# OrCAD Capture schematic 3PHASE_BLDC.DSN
size B
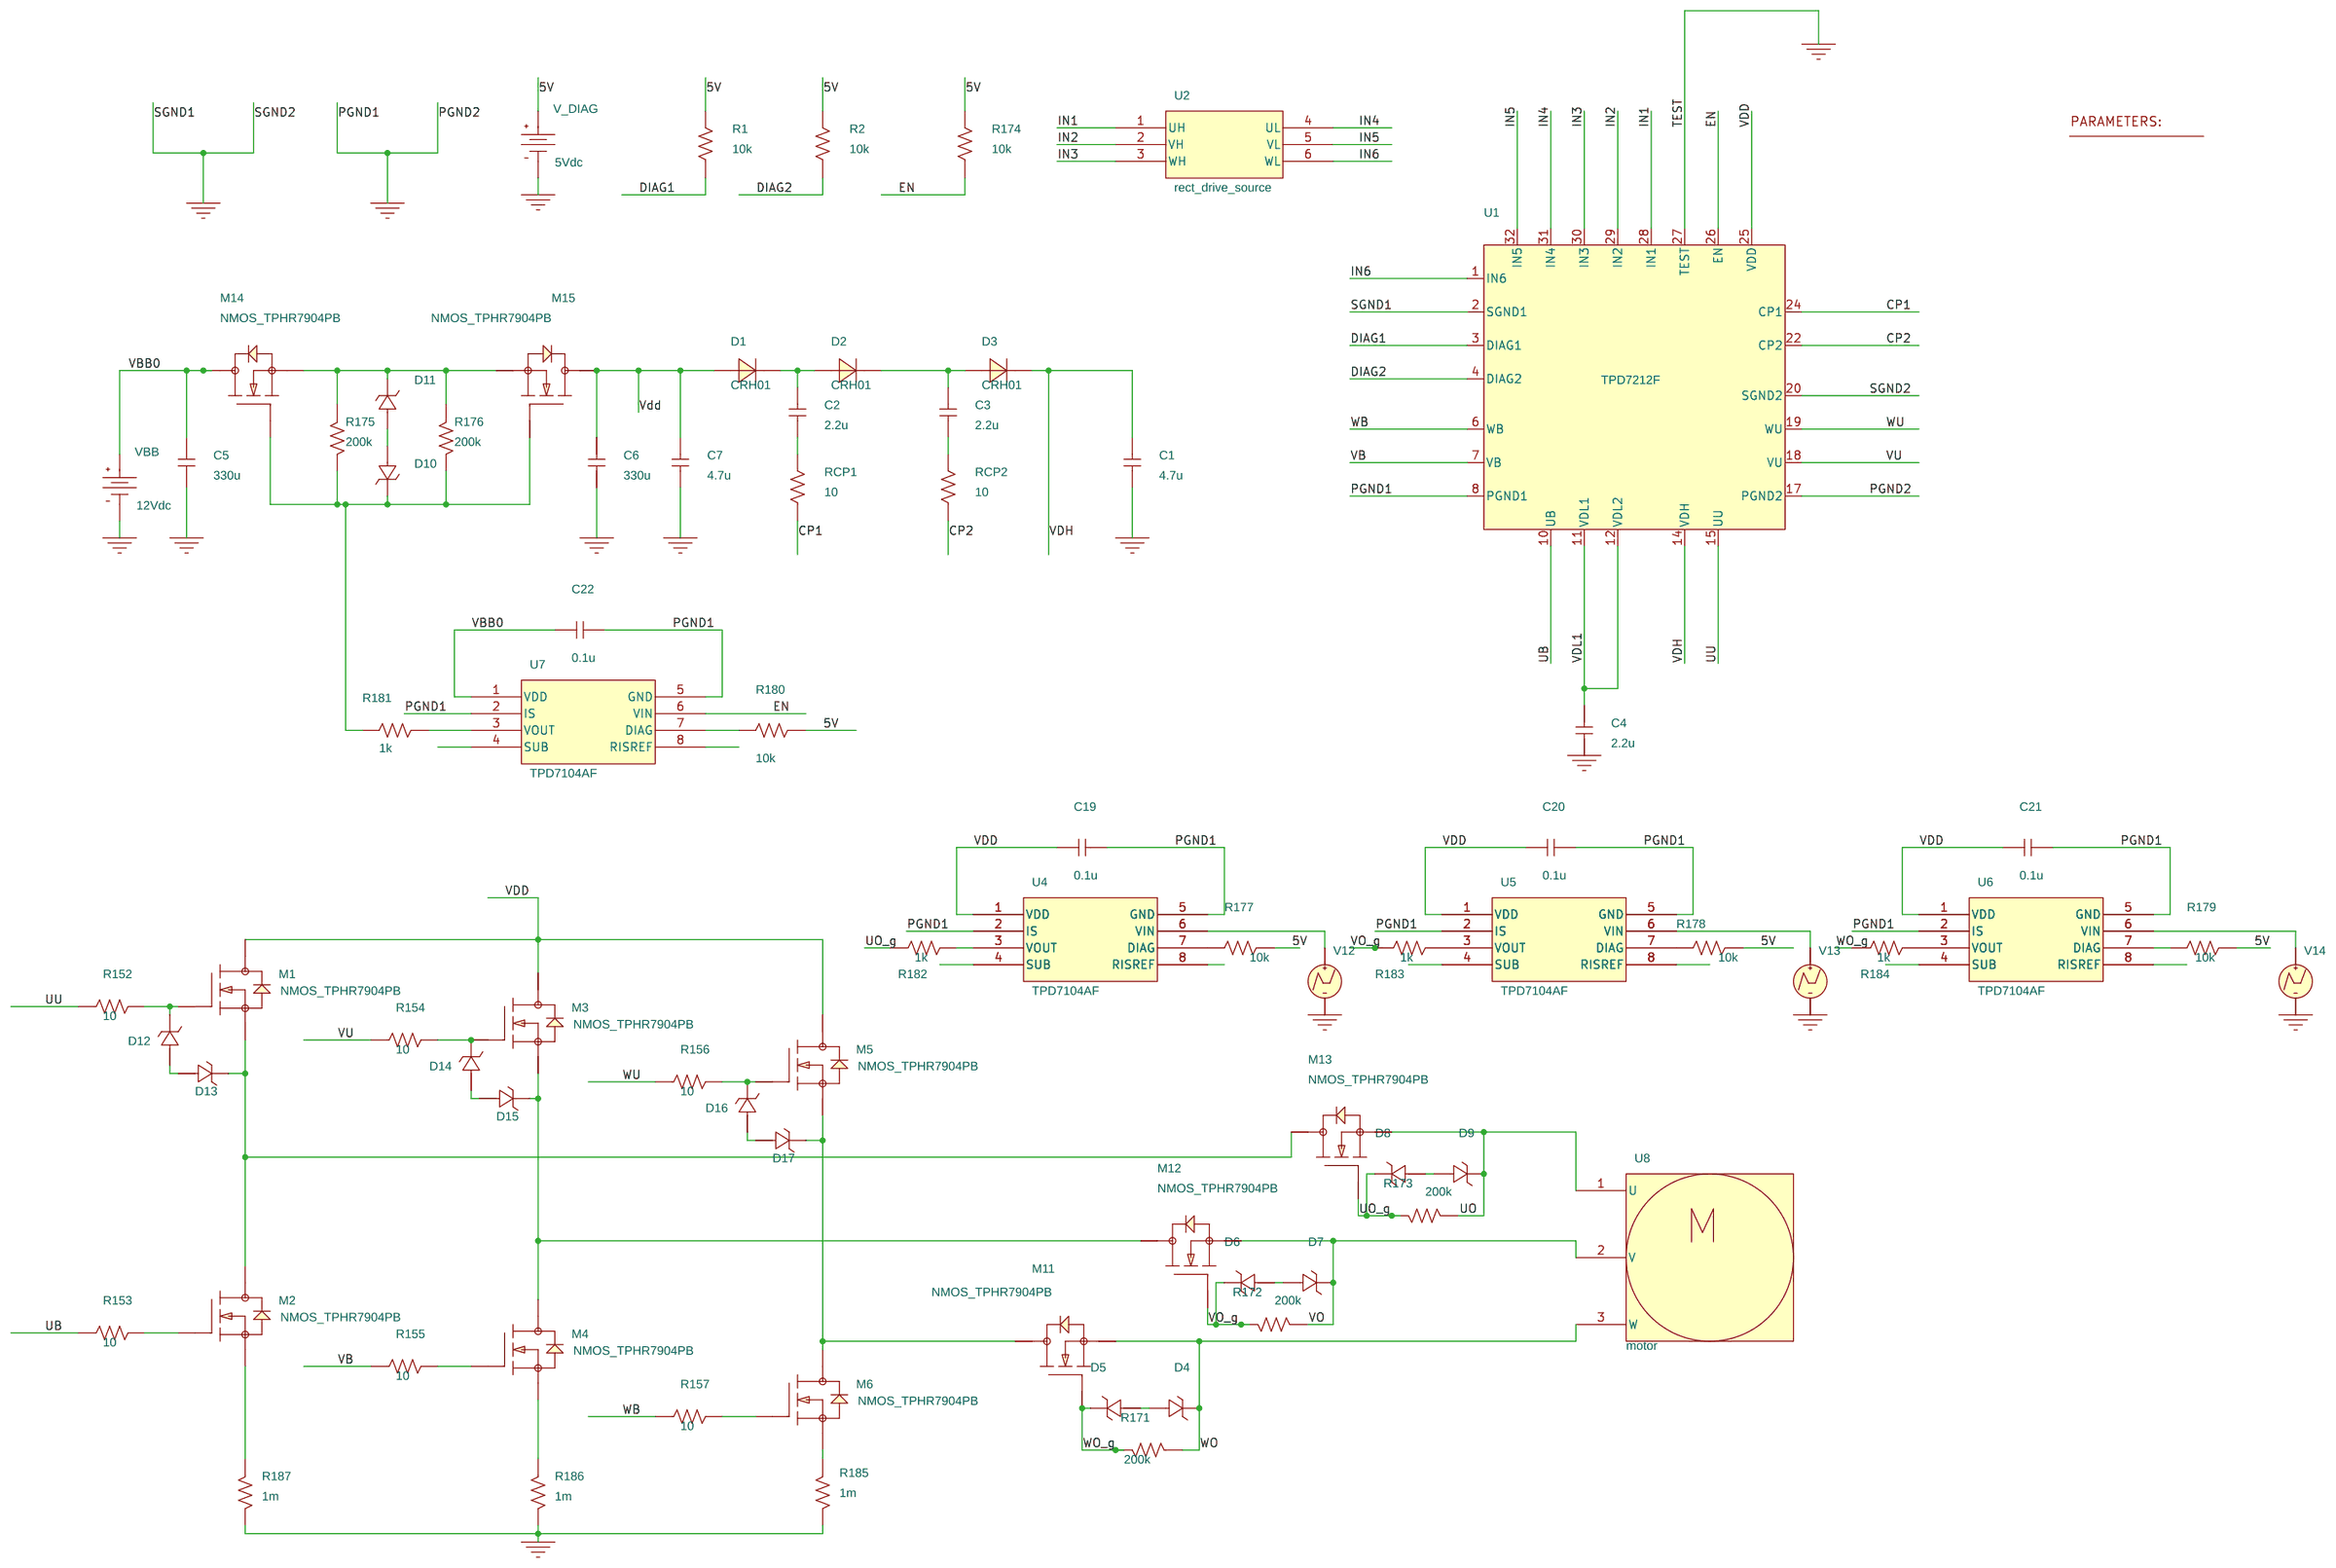
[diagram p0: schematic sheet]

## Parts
1  PARAM
C1  4.7u  [RAD/CK05]
C2  2.2u  [RAD/CK05]
C3  2.2u  [RAD/CK05]
C4  2.2u  [RAD/CK05]
C5  330u  [RAD/CK05]
C6  330u  [RAD/CK05]
C7  4.7u  [RAD/CK05]
C19  0.1u  [RAD/CK05]
C20  0.1u  [RAD/CK05]
C21  0.1u  [RAD/CK05]
C22  0.1u  [RAD/CK05]
D1  CRH01
D2  CRH01
D3  CRH01
D4  CRZ16
D5  CRZ16
D6  CRZ16
D7  CRZ16
D8  CRZ16
D9  CRZ16
D10  CRZ16
D11  CRZ16
D12  CRZ16
D13  CRZ16
D14  CRZ16
D15  CRZ16
D16  CRZ16
D17  CRZ16
M1  NMOS_TPHR7904PB
M2  NMOS_TPHR7904PB
M3  NMOS_TPHR7904PB
M4  NMOS_TPHR7904PB
M5  NMOS_TPHR7904PB
M6  NMOS_TPHR7904PB
M11  NMOS_TPHR7904PB
M12  NMOS_TPHR7904PB
M13  NMOS_TPHR7904PB
M14  NMOS_TPHR7904PB
M15  NMOS_TPHR7904PB
R1  10k  [AX/RC05]
R2  10k  [AX/RC05]
R152  10  [AX/RC05]
R153  10  [AX/RC05]
R154  10  [AX/RC05]
R155  10  [AX/RC05]
R156  10  [AX/RC05]
R157  10  [AX/RC05]
R171  200k  [AX/RC05]
R172  200k  [AX/RC05]
R173  200k  [AX/RC05]
R174  10k  [AX/RC05]
R175  200k  [AX/RC05]
R176  200k  [AX/RC05]
R177  10k  [AX/RC05]
R178  10k  [AX/RC05]
R179  10k  [AX/RC05]
R180  10k  [AX/RC05]
R181  1k  [AX/RC05]
R182  1k  [AXRC05]
R183  1k  [AXRC05]
R184  1k  [AXRC05]
R185  1m  [AX/RC05]
R186  1m  [AX/RC05]
R187  1m  [AX/RC05]
RCP1  10  [AX/RC05]
RCP2  10  [AX/RC05]
U1  TPD7212F
U2  rect_drive_source
U4  TPD7104AF
U5  TPD7104AF
U6  TPD7104AF
U7  TPD7104AF
U8  motor
V12  VPWL
V13  VPWL
V14  VPWL
V_DIAG  VDC
VBB  VDC

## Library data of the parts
1 = PARAM: Dp: 0.586; fcar: 20k
C1-C7 C19-C22 = C
D1-D3 = CRH01
D4-D17 = CRZ16
M1-M6 M11-M15 = NMOS_TPHR7904PB
R1 R2 R152-R157 R171-R187 RCP1 RCP2 = R
U1 = TPD7212F
U2 = rect_drive_source
U4-U7 = TPD7104AF
U8 = motor
V12-V14 = VPWL: T1: 0; T2: 40m; T3: 40.001m; V1: 5; V2: 5; V3: 0
V_DIAG = VDC: DC: 5Vdc
VBB = VDC: DC: 12Vdc

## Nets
5V: R1.2 R2.2 R174.2 R177.1 R178.1 R179.1 R180.1 V_DIAG.0(+)
VDD: C6.1 C7.1 C19.2 C20.2 C21.2 D1.1 M1.1 M3.1 M5.1 M15.1 U1.25(VDD) U4.1(VDD) U5.1(VDD) U6.1(VDD)
0: C1.2 C4.2 C5.2 C6.2 C7.2 C19.1 C20.1 C21.1 C22.1 R185.2 R186.2 R187.2 U1.2(SGND1) U1.8(PGND1) U1.17(PGND2) U1.20(SGND2) U1.27(TEST) U4.2(IS) U4.5(GND) U5.2(IS) U5.5(GND) U6.2(IS) U6.5(GND) U7.2(IS) U7.5(GND) V12.2(-) V13.2(-) V14.2(-) V_DIAG.1(-) VBB.1(-)
CP1: RCP1.1 U1.24(CP1)
CP2: RCP2.1 U1.22(CP2)
DIAG1: R1.1 U1.3(DIAG1)
DIAG2: R2.1 U1.4(DIAG2)
EN: R174.1 U1.26(EN) U7.6(VIN)
IN1: U1.28(IN1) U2.1(UH)
IN2: U1.29(IN2) U2.2(VH)
IN3: U1.30(IN3) U2.3(WH)
IN4: U1.31(IN4) U2.4(UL)
IN5: U1.32(IN5) U2.5(VL)
IN6: U1.1(IN6) U2.6(WL)
UB: R153.1 U1.10(UB)
UO: D9.1(2) M13.3 R173.1 U8.1(U)
UO_g: D8.1(2) M13.2 R173.2 R182.1
UU: R152.1 U1.15(UU)
VB: R155.1 U1.7(VB)
VBB0: C5.1 C22.2 M14.1 U7.1(VDD) VBB.0(+)
VDH: C1.1 D3.2 U1.14(VDH)
VDL1: C4.1 U1.11(VDL1) U1.12(VDL2)
VO: D7.1(2) M12.3 R172.1 U8.2(V)
VO_g: D6.1(2) M12.2 R172.2 R183.1
VU: R154.1 U1.18(VU)
WB: R157.1 U1.6(WB)
WO: D4.1(2) M11.3 R171.1 U8.3(W)
WO_g: D5.1(2) M11.2 R171.2 R184.1
WU: R156.1 U1.19(WU)
N5522946: D11.1(2) M14.3 M15.3 R175.1 R176.1
N5523000: C2.2 D1.2 D2.1
N5523018: C3.2 D2.2 D3.1
N5523146: D10.1(2) M14.2 M15.2 R175.2 R176.2 R181.2
N5523154: C2.1 RCP1.2
N5523162: C3.1 RCP2.2
N5523686: R181.1 U7.3(VOUT)
N5523692: R180.2 U7.7(DIAG)
N5524070: U4.6(VIN) V12.1(+)
N5524130: U5.6(VIN) V13.1(+)
N5524190: U6.6(VIN) V14.1(+)
N5524230: R182.2 U4.3(VOUT)
N5524272: R179.2 U6.7(DIAG)
N5524474: D12.1(2) M1.2 R152.2
N5524502: D13.1(2) M1.3 M2.1 M13.1
N5524514: D14.1(2) M3.2 R154.2
N5524546: D15.1(2) M3.3 M4.1 M12.1
N5524578: D16.1(2) M5.2 R156.2
N5524698: D17.1(2) M5.3 M6.1 M11.1
N5525156: M2.2 R153.2
N5525256: M4.2 R155.2
N5525294: M6.2 R157.2
N5527687: R177.2 U4.7(DIAG)
N5527688: R183.2 U5.3(VOUT)
N5527689: R178.2 U5.7(DIAG)
N5527690: R184.2 U6.3(VOUT)
N5528150: D4.0(1) D5.0(1)
N5528338: D6.0(1) D7.0(1)
N5528425: D8.0(1) D9.0(1)
N5528506: D10.0(1) D11.0(1)
N5528676: D12.0(1) D13.0(1)
N5528807: D14.0(1) D15.0(1)
N5528912: D16.0(1) D17.0(1)
N5529951: M6.3 R185.1
N5530554: M4.3 R186.1
N5530558: M2.3 R187.1

Not connected (* = marked no-connect by the designer): U4 4(SUB) 8(RISREF); U5 4(SUB) 8(RISREF); U6 4(SUB) 8(RISREF); U7 4(SUB) 8(RISREF)
